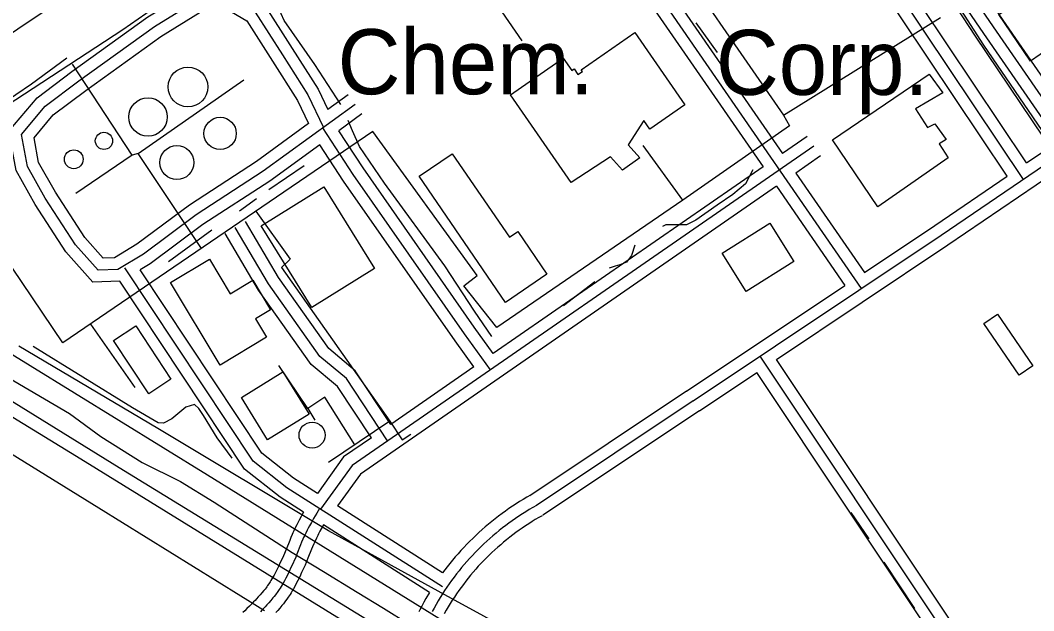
# Model space of a CAD drawing. Extents: x 3355724 to 3393621, y 594744 to 620174.
# Drawn here: x 3384707 to 3386000, y 616090 to 616843 of the extents above; entities that cross this region are included whole.
import ezdxf

# ---------------------------------------------------------------- set-up
doc = ezdxf.new("R2010")
doc.units = 0
for name, color, linetype in [('V-BLDG-IDEN', 7, 'Continuous'), ('V-BLDG-OTLN', 7, 'Continuous'), ('V-DOMW-TANK', 7, 'Continuous'), ('V-RAIL-TRAK', 7, 'Continuous'), ('V-ROAD-CNTR', 7, 'Continuous'), ('V-SITE-OTLN', 7, 'Continuous'), ('V-TOPO-SHOR', 7, 'Continuous'), ('V-UTIL-LINE', 7, 'Continuous')]:
    doc.layers.add(name, color=color, linetype=linetype)

msp = doc.modelspace()

# ---------------------------------------------------------------- linework, layer by layer
at = {"layer": 'V-BLDG-OTLN'}
for points in [[(3385996.2, 616791), (3385955.7, 616850.4), (3386005, 616884), (3386047.4, 616821.8), (3386035.4, 616813.6), (3386033.4, 616816.5)], [(3385410.4, 616636), (3385332.7, 616747.8), (3385400.1, 616794.7), (3385411.1, 616778.9), (3385414, 616781), (3385418.9, 616773.9), (3385424.5, 616777.8), (3385423.1, 616779.8), (3385491.3, 616827.2), (3385555.3, 616735), (3385510.7, 616704), (3385502.8, 616715.3), (3385482.9, 616684.2), (3385497.9, 616667.6), (3385475.9, 616651.9), (3385460.3, 616668.6)], [(3385743.7, 616690.6), (3385866.8, 616774.3), (3385884.2, 616750.5), (3385849.7, 616730), (3385864.8, 616706.2), (3385874.3, 616711), (3385888.8, 616690.8), (3385879.8, 616685.4), (3385891.3, 616667.6), (3385801.5, 616604.9)], [(3385258.5, 616672.7), (3385331.4, 616566.3), (3385342, 616573.6), (3385379.3, 616519.2), (3385326.5, 616483), (3385216.4, 616643.9)], [(3385094.9, 616630.4), (3385159.3, 616526.2), (3385079.2, 616476.6), (3385014.8, 616580.8)], [(3385694.5, 616535.2), (3385633.4, 616496.8), (3385602.7, 616545.7), (3385663.7, 616584.1)], [(3384962.3, 616402.9), (3384899.3, 616508.3), (3384949, 616538), (3384975.3, 616494), (3385004.2, 616511.3), (3385026.8, 616473.6), (3385007.6, 616462.1), (3385021.7, 616438.5)], [(3385981.9, 616390.3), (3385936.9, 616456.1), (3385954, 616467.9), (3385999.1, 616402)], [(3384871.3, 616366.5), (3384826.4, 616434.2), (3384854.7, 616452.9), (3384899.6, 616385.2)], [(3385075.8, 616340.4), (3385022.9, 616307.8), (3384989.7, 616361.6), (3385042.5, 616394.3)]]:
    msp.add_lwpolyline(points, close=True, dxfattribs=at)
at = {"layer": 'V-DOMW-TANK'}
for centre, radius in [((3384921.4, 616757.9), 25.3), ((3384870.4, 616719.6), 24.5), ((3384962.4, 616698.6), 20.6), ((3384814.2, 616689.1), 11), ((3384775.7, 616665.6), 12), ((3384907.2, 616661.4), 21.7), ((3385079.7, 616313.6), 16.6)]:
    msp.add_circle(centre, radius, dxfattribs=at)
at = {"layer": 'V-RAIL-TRAK'}
for points in [[(3381392.5, 618368.6), (3381453.7, 618331.1), (3381683.8, 618189.1), (3381827.4, 618100.5), (3382106.7, 617931.3), (3382450.5, 617718.6), (3382821.1, 617490.4), (3383172.7, 617274.6), (3383310.3, 617189.7), (3383574, 617026.9), (3383928.8, 616809.6), (3384345, 616552.6), (3384784.8, 616283.3), (3385205.7, 616023.4), (3385478.7, 615856.3), (3385795, 615660.7), (3385897.3, 615598.6)], [(3385904.3, 615614.3), (3385683.2, 615750.2), (3385570.6, 615818.9), (3385413.3, 615914.7), (3385214, 616038.3), (3385149, 616078.5), (3384833.5, 616271.8), (3384538.4, 616454.3), (3384221.4, 616648.3), (3383918.5, 616835.4)], [(3384032.5, 616827.3), (3384049, 616817.1), (3384210.9, 616716.8), (3384439.8, 616575), (3384663.1, 616437.2), (3384946.4, 616262.8), (3385241.6, 616079.9), (3385277.1, 616058), (3385529.6, 615913.2), (3385760, 615773.1), (3385838.2, 615724.9), (3385898.9, 615687.4)]]:
    msp.add_lwpolyline(points, dxfattribs=at)
at = {"layer": 'V-ROAD-CNTR'}
for points in [[(3384890, 618380.8), (3385050.7, 618146), (3385351.1, 617710.5), (3385675.8, 617233.1), (3385948.8, 616834.8), (3386180.2, 616499.2)], [(3385408.6, 617599.4), (3385663.4, 617224.7), (3385936.4, 616826.3), (3386031.5, 616688.4)], [(3385991.1, 616660.9), (3385588.1, 617263.9)], [(3385987.1, 616640), (3385577.1, 617253.2)], [(3385565.7, 616357.2), (3385882.4, 616568.8), (3386237.9, 616810.7), (3386505, 616997.5), (3386696.5, 617128.4), (3386844.1, 617231.4)], [(3385342, 617135.8), (3385780.4, 616500.6)], [(3385764, 617131), (3385961.1, 616843.3), (3386056.3, 616705.3)], [(3385966.3, 616644.1), (3385664.1, 617096.2)], [(3385482.4, 616958.9), (3385679.8, 616672.8)], [(3385458.4, 616940.8), (3385655.1, 616655.8)], [(3384834.3, 616509.9), (3384800.2, 616508.9), (3384765.7, 616547.4), (3384726.5, 616608.1), (3384702.4, 616651.1), (3384693, 616701.5), (3384728.8, 616744.2), (3384773.1, 616777.7), (3384870.3, 616847.5), (3384926.6, 616882), (3384975.8, 616889.3), (3385017.8, 616864.6), (3385054.5, 616807), (3385087.6, 616755.3), (3385100, 616729.1)], [(3385134.5, 616735.7), (3385017.4, 616650.3), (3384931.8, 616594.8), (3384864.6, 616544.7), (3384832.1, 616524.9), (3384806.7, 616524.1), (3384777.7, 616556.5), (3384739.3, 616615.8), (3384716.6, 616656.2), (3384709.1, 616697.3), (3384739.2, 616733.3), (3384782, 616765.6), (3384878.6, 616835), (3384931.9, 616867.6), (3384972.8, 616873.7), (3385007.1, 616853.5), (3385041.9, 616798.9), (3385074.4, 616748), (3385094.2, 616706.2)], [(3385075.3, 616711.1), (3385008.9, 616662.7), (3384923.2, 616607.1), (3384856.1, 616557.2), (3384827.6, 616539.7), (3384813.3, 616539.3), (3384789.6, 616565.6), (3384752.2, 616623.6), (3384730.9, 616661.4), (3384725.1, 616693), (3384749.6, 616722.3), (3384790.9, 616753.5), (3384886.9, 616822.5), (3384937.1, 616853.2), (3384969.7, 616858.1), (3384996.4, 616842.4), (3385029.3, 616790.8), (3385061.2, 616740.7), (3385075.3, 616711.1)], [(3385125.7, 616747.8), (3385100, 616729.1)], [(3385143.3, 616723.6), (3385113.7, 616701.9)], [(3385307.3, 616397), (3385274.3, 616442.7), (3385132.3, 616646.1), (3385093.3, 616705.6)], [(3385310.9, 616417.7), (3385286.5, 616451.4), (3385144.7, 616654.5), (3385113.7, 616701.9)], [(3385711.3, 616694.6), (3385679.8, 616672.8)], [(3385089.4, 616684.2), (3385025.9, 616637.9), (3384940.4, 616582.5), (3384873, 616532.3), (3384860.5, 616524.7)], [(3385286.2, 616400.6), (3385262.1, 616434), (3385119.9, 616637.7), (3385089.4, 616684.2)], [(3385719.8, 616682.3), (3385130.7, 616274.9), (3385090.6, 616219)], [(3385991.1, 616660.9), (3386031.5, 616688.4)], [(3385728.3, 616669.9), (3385696.8, 616648.1)], [(3385655.1, 616655.8), (3385310.9, 616417.7)], [(3385672.3, 616410.3), (3385890.8, 616556.4), (3386048.5, 616663.7)], [(3385696.8, 616648.1), (3385784.4, 616521.3)], [(3385784.4, 616521.3), (3385874, 616581.2), (3385966.3, 616644.1)], [(3385672.2, 616631.1), (3385141.4, 616264), (3385112.1, 616223.2)], [(3385672.2, 616631.1), (3385759.4, 616504.7)], [(3385176.1, 616306.3), (3385123.5, 616385.7), (3385089.8, 616413.9), (3385024.1, 616506.7), (3384981.8, 616578.5)], [(3385180.2, 616327.3), (3385134.7, 616395.8), (3385100.9, 616424.1), (3385036.7, 616514.9), (3384994.7, 616586.1)], [(3385155.5, 616310.3), (3385112.2, 616375.6), (3385078.6, 616403.6), (3385011.5, 616498.6), (3384968.9, 616570.9)], [(3385246.1, 616120), (3385047.5, 616246.5), (3385004.6, 616280.5), (3384840.9, 616527.1)], [(3385086.7, 616239.3), (3385056.2, 616258.7), (3385015.8, 616290.8), (3384860.5, 616524.7)], [(3385068.7, 616215.2), (3385038.8, 616234.3), (3384993.4, 616270.2), (3384834.3, 616509.9)], [(3385557.4, 616369.6), (3385759.4, 616504.7)], [(3386181.5, 615638.1), (3386022.3, 615876.7), (3385982.4, 615935.7), (3385892.4, 616052.2), (3385651.5, 616414.5)], [(3386009.5, 615922.4), (3385994.6, 615944.4), (3385904.6, 616061), (3385672.3, 616410.3)], [(3385286.2, 616400.6), (3385180.2, 616327.3)], [(3385574, 616344.7), (3385647.3, 616393.7)], [(3386169.1, 615629.8), (3386009.9, 615868.3), (3385970.2, 615926.9), (3385880.2, 616043.5), (3385647.3, 616393.7)], [(3385557.4, 616369.6), (3385357.5, 616236.3)], [(3385565.7, 616357.2), (3385365.8, 616223.9)], [(3385574, 616344.7), (3385374.1, 616211.4)], [(3385155.5, 616310.3), (3385120, 616285.8), (3385086.7, 616239.3)], [(3385358.4, 616236.9), (3385353.8, 616234.3), (3385349.1, 616231.5), (3385344.5, 616228.7), (3385339.9, 616225.8), (3385335.3, 616222.8), (3385330.8, 616219.8), (3385326.4, 616216.7), (3385322, 616213.5), (3385317.6, 616210.2), (3385313.3, 616206.9), (3385309.1, 616203.5), (3385304.9, 616200.1), (3385300.7, 616196.6), (3385296.6, 616193), (3385292.6, 616189.4), (3385288.6, 616185.7), (3385284.7, 616181.9), (3385280.8, 616178.1), (3385277, 616174.3), (3385273.3, 616170.3), (3385269.6, 616166.3), (3385266, 616162.3), (3385262.4, 616158.2), (3385258.9, 616154), (3385255.5, 616149.8), (3385252.1, 616145.6), (3385246.1, 616137.8)], [(3385068.7, 616215.2), (3385063.2, 616205), (3385061.4, 616201.6), (3385060.1, 616199), (3385058.2, 616195.2), (3385056.4, 616191.3), (3385055.3, 616189), (3385054.3, 616186.8), (3385052.6, 616182.8), (3385051.2, 616179.3), (3385046.5, 616167.5), (3385045.4, 616164.7), (3385044.5, 616162.6), (3385043.2, 616159.6), (3385041.9, 616156.6), (3385039.2, 616150.9), (3385036.9, 616145.9), (3385034.8, 616141.7), (3385032.9, 616138.1), (3385031.3, 616135), (3385029.8, 616132.3), (3385028.5, 616130.1), (3385027.3, 616128.1), (3385026.3, 616126.4), (3385025.3, 616125), (3385024.5, 616123.8), (3385023, 616121.6), (3385021.9, 616120), (3385021, 616118.9), (3385019.7, 616117.1), (3385018.3, 616115.4), (3385015.8, 616112.5), (3385013.4, 616109.8), (3385011.1, 616107.2), (3385009, 616104.9), (3385006.9, 616102.7), (3385005, 616100.7), (3385003.2, 616098.8), (3384999.7, 616095.3), (3384996.6, 616092.2), (3384993.8, 616089.6), (3384991.4, 616087.3)], [(3385089.2, 616220), (3385085.6, 616214.1), (3385083.5, 616210.5), (3385081.7, 616207.4), (3385080.1, 616204.6), (3385078.8, 616202.2), (3385076.4, 616197.9), (3385074.8, 616194.7), (3385073.5, 616192.3), (3385071.7, 616188.6), (3385069.9, 616184.9), (3385068.9, 616182.8), (3385068.1, 616180.8), (3385066.4, 616177), (3385065.1, 616173.7), (3385060.4, 616161.9), (3385059.3, 616159), (3385058.4, 616156.8), (3385057, 616153.6), (3385055.5, 616150.3), (3385052.8, 616144.5), (3385050.4, 616139.4), (3385048.2, 616135), (3385046.2, 616131.1), (3385044.5, 616127.8), (3385042.9, 616124.9), (3385041.4, 616122.4), (3385040.1, 616120.3), (3385038.9, 616118.4), (3385037.9, 616116.8), (3385036.9, 616115.4), (3385035.3, 616112.9), (3385034, 616111.1), (3385033, 616109.8), (3385031.4, 616107.8), (3385029.8, 616105.8), (3385027.2, 616102.7), (3385024.6, 616099.8), (3385022.2, 616097.2), (3385020, 616094.7), (3385017.8, 616092.4), (3385015.8, 616090.3), (3385013.9, 616088.3)], [(3385246.1, 616137.8), (3385112.1, 616223.2)], [(3385365.8, 616223.9), (3385361.3, 616221.3), (3385356.8, 616218.6), (3385352.4, 616215.9), (3385348, 616213.2), (3385343.6, 616210.3), (3385339.3, 616207.4), (3385335.1, 616204.4), (3385330.8, 616201.4), (3385326.7, 616198.3), (3385322.6, 616195.1), (3385318.5, 616191.9), (3385314.5, 616188.6), (3385310.5, 616185.2), (3385306.6, 616181.8), (3385302.7, 616178.3), (3385298.9, 616174.8), (3385295.1, 616171.2), (3385291.4, 616167.5), (3385287.8, 616163.8), (3385284.2, 616160.1), (3385280.7, 616156.2), (3385277.2, 616152.4), (3385273.8, 616148.4), (3385270.5, 616144.5), (3385267.2, 616140.4), (3385264, 616136.4), (3385260.8, 616132.2), (3385257.7, 616128.1), (3385254.7, 616123.8), (3385251.7, 616119.6), (3385248.8, 616115.2), (3385246, 616110.9), (3385243.2, 616106.5), (3385240.5, 616102), (3385237.9, 616097.6), (3385235.3, 616093), (3385232.8, 616088.5)], [(3385094.1, 616199), (3385089.7, 616190.9), (3385088.1, 616187.8), (3385086.9, 616185.5), (3385085.2, 616182), (3385083.5, 616178.5), (3385082.6, 616176.6), (3385081.8, 616174.8), (3385080.3, 616171.2), (3385079, 616168.1), (3385074.4, 616156.4), (3385073.1, 616153.3), (3385072.2, 616151), (3385070.7, 616147.5), (3385069.1, 616144.1), (3385066.4, 616138.1), (3385063.9, 616132.9), (3385061.6, 616128.2), (3385059.5, 616124.2), (3385057.6, 616120.6), (3385055.9, 616117.5), (3385054.3, 616114.8), (3385052.9, 616112.4), (3385051.6, 616110.4), (3385050.4, 616108.6), (3385049.4, 616107), (3385047.5, 616104.3), (3385046, 616102.2), (3385044.9, 616100.7), (3385043.1, 616098.4), (3385041.3, 616096.2), (3385038.5, 616092.9), (3385035.9, 616089.9), (3385033.4, 616087.1)], [(3385229.4, 616112.8), (3385094.1, 616199)], [(3385373.2, 616210.8), (3385368.8, 616208.3), (3385364.5, 616205.8), (3385360.3, 616203.2), (3385356.1, 616200.5), (3385351.9, 616197.8), (3385347.8, 616195), (3385343.7, 616192.2), (3385339.7, 616189.3), (3385335.7, 616186.3), (3385331.8, 616183.3), (3385327.9, 616180.2), (3385324.1, 616177), (3385320.3, 616173.8), (3385316.5, 616170.6), (3385312.8, 616167.2), (3385309.2, 616163.9), (3385305.6, 616160.4), (3385302.1, 616156.9), (3385298.6, 616153.4), (3385295.2, 616149.8), (3385291.8, 616146.2), (3385288.5, 616142.5), (3385285.2, 616138.7), (3385282, 616134.9), (3385278.9, 616131), (3385275.8, 616127.1), (3385272.8, 616123.2), (3385269.8, 616119.2), (3385266.9, 616115.2), (3385264.1, 616111.1), (3385261.3, 616107), (3385258.6, 616102.8), (3385256, 616098.6), (3385253.4, 616094.4), (3385250.9, 616090.1), (3385248.4, 616085.7)], [(3385229.4, 616112.8), (3385224.9, 616105), (3385222.2, 616100.3), (3385219.6, 616095.5), (3385217.1, 616090.8), (3385215.8, 616088.3)]]:
    msp.add_lwpolyline(points, dxfattribs=at)
at = {"layer": 'V-SITE-OTLN'}
for p, q in [((3384838.3, 616831.3), (3384973.2, 616925.2)), ((3384629.6, 616694.6), (3384838.3, 616831.3)), ((3384883.1, 616322), (3384705.8, 616427.1)), ((3385100.5, 616191.4), (3384883.1, 616322)), ((3385257.4, 616105.2), (3385100.5, 616191.4)), ((3385441.1, 616005.5), (3385257.4, 616105.2))]:
    msp.add_line(p, q, dxfattribs=at)
at = {"layer": 'V-TOPO-SHOR'}
for p, q in [((3385596.9, 616801.7), (3385569.9, 616839.7)), ((3385024.6, 616627), (3385069.7, 616657.7)), ((3384987.3, 616600), (3385008.6, 616615.6)), ((3384896.6, 616535.2), (3384951.7, 616575.4)), ((3385440.3, 616509.3), (3385400.6, 616478.7)), ((3385767.2, 616215), (3385790, 616181.2)), ((3385809.3, 616151.5), (3385848.3, 616092.2))]:
    msp.add_line(p, q, dxfattribs=at)
for points in [[(3385284.3, 617200), (3385241.6, 617174.7), (3385184, 617153.5), (3385139.4, 617132.4), (3385114, 617113.2), (3385049.3, 617069.9), (3384996, 617030.3), (3384944.3, 616999.7), (3384940.7, 616997.5), (3384931.3, 616991.8), (3384833.5, 616921), (3384783.7, 616885), (3384757.6, 616866.9), (3384716.1, 616839.9), (3384678.7, 616814.7)], [(3385347.8, 616816.6), (3385296.8, 616891.3), (3385245.1, 616969.6), (3385209.1, 617024.1)], [(3385820.8, 616991.1), (3385936.3, 616811.2), (3386359.6, 616191.4), (3386378.9, 616141.6), (3386490.4, 615996.2), (3386586.6, 615847), (3386602, 615820.2), (3387114.8, 616174.2)], [(3385116.3, 616735.4), (3385083.2, 616786.4), (3385044.2, 616842.7), (3385036.3, 616859.9), (3385033.3, 616868.2), (3385028.5, 616874.8), (3385018.3, 616884.8), (3385013.5, 616889.5)], [(3384766.9, 616794.6), (3384721.8, 616761.6), (3384661.3, 616720.7), (3384645.3, 616710.5), (3384638.2, 616708.7), (3384628, 616715.7), (3384612.4, 616741.8), (3384593.1, 616778.1)], [(3385309.2, 616439.4), (3385287, 616472), (3385249.1, 616529.5), (3385172.2, 616635.1), (3385140.4, 616681.9), (3385131.4, 616702.1), (3385125.9, 616715.2)], [(3384245, 616665.6), (3384298.8, 616631.4), (3384360.9, 616596), (3384484, 616514.6), (3384515.7, 616495.7), (3384547.4, 616475.1), (3384607.1, 616440.3), (3384647.2, 616413.2), (3384770.3, 616341.3), (3384810.4, 616311.7), (3384862.9, 616278.7), (3384911.9, 616254.6), (3384954.9, 616228.1), (3385054.2, 616163.8), (3385094.2, 616139.6), (3385137.2, 616113), (3385170.7, 616093), (3385203.6, 616072.4)], [(3385641.9, 616652.2), (3385632.5, 616634.3), (3385616.5, 616620.5), (3385596.4, 616607.2), (3385569.1, 616588), (3385557.2, 616582), (3385531, 616581.8), (3385526.9, 616580)], [(3385491.3, 616556), (3385487.2, 616542.9), (3385480.7, 616534.5), (3385472.4, 616530.9), (3385466.4, 616529.1), (3385458.7, 616526.6)], [(3384297.4, 616544.1), (3384415.7, 616468.6), (3384608.8, 616343.6), (3384807.8, 616220.9), (3385018.8, 616090)], [(3384977.8, 616284.2), (3384958.6, 616310.2), (3384941.2, 616338.7), (3384935.2, 616347.6), (3384929.8, 616352.9), (3384918.5, 616349.3), (3384900.7, 616334.3), (3384890, 616328.9), (3384883.5, 616329.4), (3384850.6, 616348.3), (3384723.9, 616426.7)]]:
    msp.add_lwpolyline(points, dxfattribs=at)
at = {"layer": 'V-UTIL-LINE'}
for p, q in [((3384850.1, 616671), (3384774, 616786.9)), ((3384797, 616455.1), (3384853.6, 616374.2)), ((3385074.5, 616347.7), (3385037.4, 616402.4))]:
    msp.add_line(p, q, dxfattribs=at)
for points in [[(3385513.8, 616964), (3385681.2, 616721.9), (3385881.5, 616846.4)], [(3386234.3, 615225.7), (3386214.6, 615265.2), (3386383.2, 615378.2), (3386266.1, 615554.6), (3386555.9, 615752.3), (3386600.5, 615781.2), (3386513.7, 615911.1), (3386377.9, 616110.4), (3386311.3, 616206.8), (3386332.2, 616224.2), (3386229.3, 616379.6), (3386114.3, 616546.1), (3386052.5, 616636.6), (3386049.8, 616641.2), (3386017.5, 616689.1), (3386012.8, 616693.7), (3385926, 616822.8), (3385901.8, 616859.9)], [(3384938.5, 616551.8), (3384857.7, 616672.8), (3384992.7, 616767.1)], [(3385681.2, 616721.9), (3385688.9, 616708.5), (3385552.7, 616613.6), (3385502, 616683.4)], [(3385552.7, 616613.6), (3385315.2, 616450.8), (3385273.4, 616504.3), (3385290.3, 616517.3), (3385157.1, 616701.2), (3384761.9, 616431.2), (3384605.7, 616662.2), (3384553.3, 616625.7)], [(3384857.7, 616672.8), (3384850.1, 616671), (3384778.5, 616622.1)], [(3385008, 616599.3), (3385051.7, 616538.2), (3385040.6, 616527.6), (3385179.1, 616331.5), (3385100.6, 616278.5)], [(3385134.4, 616301.3), (3385096.1, 616361.9), (3385074.5, 616347.7), (3385083.4, 616332.6)], [(3385179.1, 616331.5), (3385194.5, 616307.7), (3385205.5, 616314.7)]]:
    msp.add_lwpolyline(points, dxfattribs=at)

# ---------------------------------------------------------------- texts
at = {"layer": 'V-BLDG-IDEN'}
for s, p in [('Chem.', (3385112.3, 616748.6)), ('Corp.', (3385594.9, 616747.8))]:
    msp.add_text(s, height=83, dxfattribs=at).set_placement(p)

doc.saveas('drawing.dxf')
